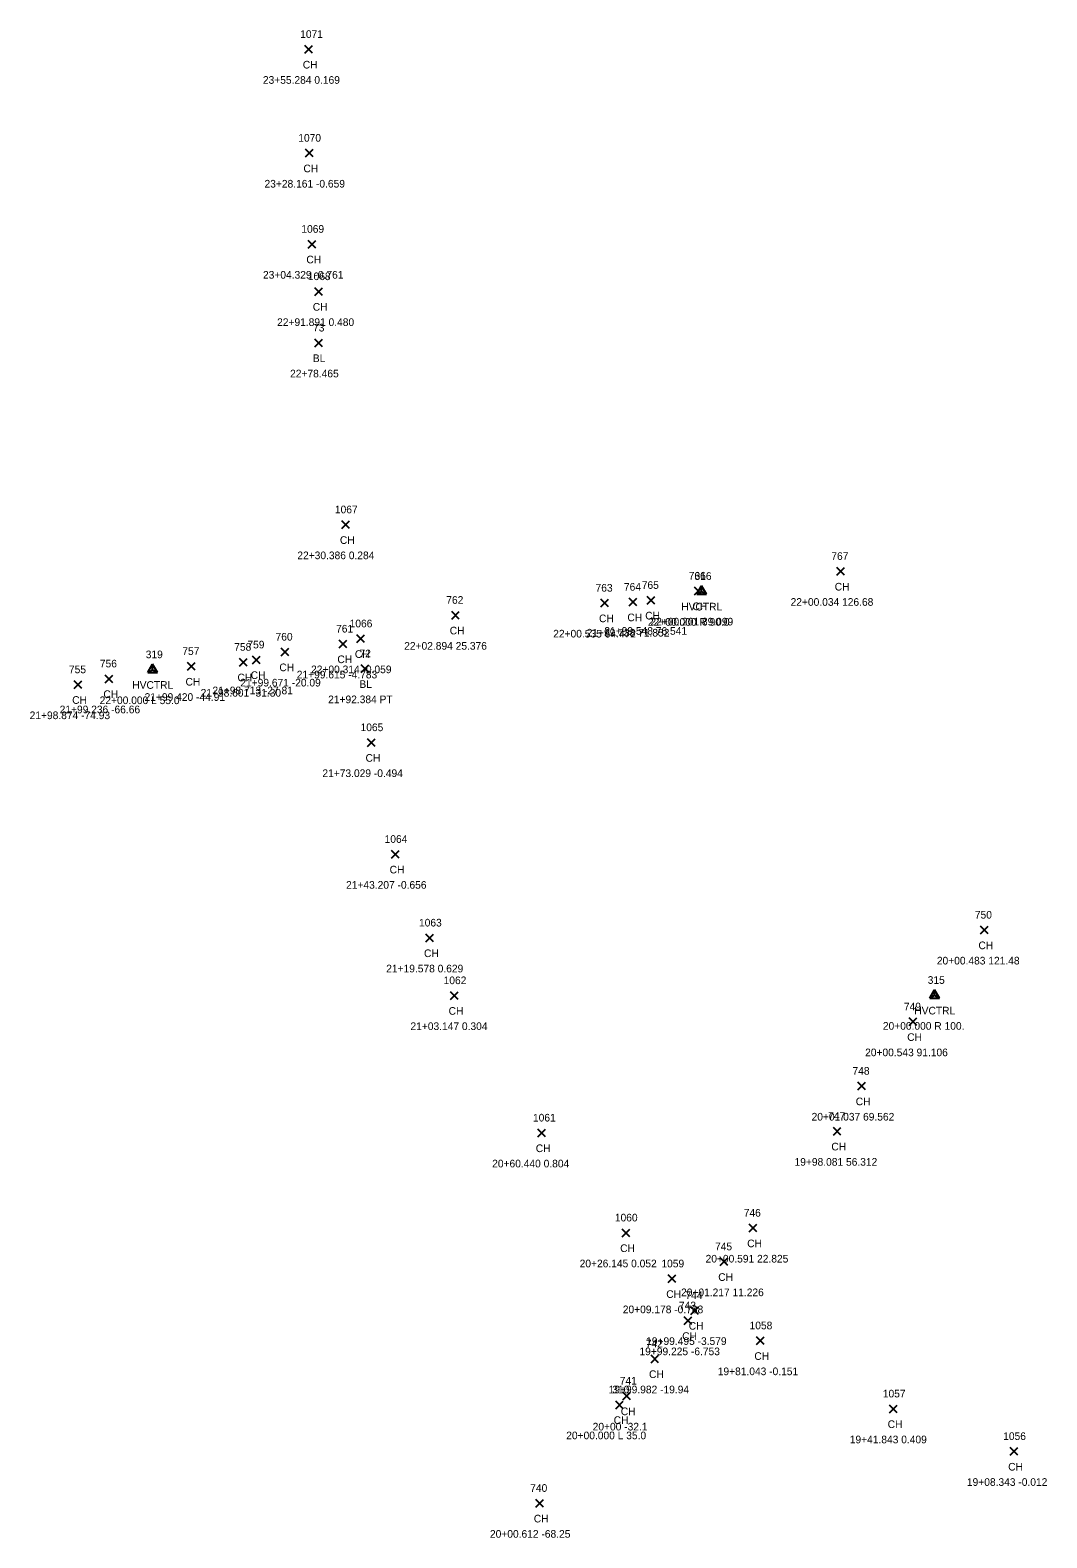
# Model space of a CAD drawing. Extents: x 89316 to 92454, y 84175 to 86051.
# Drawn here: x 90198.7 to 90464.6, y 85155.5 to 85549.8 of the extents above; entities that cross this region are included whole.
import ezdxf

# ---------------------------------------------------------------- set-up
doc = ezdxf.new("R2010")
doc.units = 0
for name, color, linetype in [('C_A', 7, 'Continuous'), ('C_C', 7, 'Continuous'), ('C_I', 7, 'Continuous'), ('C_TIC', 7, 'Continuous'), ('CPSM', 7, 'Continuous'), ('L_A', 7, 'Continuous'), ('L_C', 7, 'Continuous'), ('L_I', 7, 'Continuous'), ('L_TIC', 7, 'Continuous')]:
    doc.layers.add(name, color=color, linetype=linetype)

msp = doc.modelspace()

# ---------------------------------------------------------------- linework, layer by layer
at = {"layer": 'C_TIC'}
for points in [[(90273.17, 85466.95), (90275.17, 85468.95)], [(90275.17, 85466.95), (90273.17, 85468.95)], [(90285.34, 85381.74), (90287.34, 85383.74)], [(90287.34, 85381.74), (90285.34, 85383.74)]]:
    msp.add_lwpolyline(points, dxfattribs=at)
at = {"layer": 'CPSM'}
for p, q in [((90373.08, 85402.27), (90374.33, 85404.43)), ((90373.08, 85402.27), (90374.33, 85402.99)), ((90373.08, 85402.27), (90375.58, 85402.27)), ((90375.58, 85402.27), (90374.33, 85404.43)), ((90374.33, 85402.99), (90374.33, 85404.43)), ((90374.33, 85402.99), (90374.33, 85402.99)), ((90374.33, 85402.99), (90375.58, 85402.27)), ((90229.5, 85381.78), (90230.75, 85383.94)), ((90229.5, 85381.78), (90230.75, 85382.5)), ((90229.5, 85381.78), (90232, 85381.78)), ((90232, 85381.78), (90230.75, 85383.94)), ((90230.75, 85382.5), (90230.75, 85383.94)), ((90230.75, 85382.5), (90230.75, 85382.5)), ((90230.75, 85382.5), (90232, 85381.78)), ((90434.02, 85296.62), (90435.27, 85298.79)), ((90434.02, 85296.62), (90435.27, 85297.34)), ((90434.02, 85296.62), (90436.52, 85296.62)), ((90436.52, 85296.62), (90435.27, 85298.79)), ((90435.27, 85297.34), (90435.27, 85298.79)), ((90435.27, 85297.34), (90435.27, 85297.34)), ((90435.27, 85297.34), (90436.52, 85296.62))]:
    msp.add_line(p, q, dxfattribs=at)
at = {"layer": 'L_TIC'}
for points in [[(90270.55, 85543.73), (90272.55, 85545.73)], [(90272.55, 85543.73), (90270.55, 85545.73)], [(90270.71, 85516.59), (90272.71, 85518.59)], [(90272.71, 85516.59), (90270.71, 85518.59)], [(90271.47, 85492.77), (90273.47, 85494.77)], [(90273.47, 85492.77), (90271.47, 85494.77)], [(90273.16, 85480.39), (90275.16, 85482.39)], [(90275.16, 85480.39), (90273.16, 85482.39)], [(90280.25, 85419.4), (90282.25, 85421.4)], [(90282.25, 85419.4), (90280.25, 85421.4)], [(90409.67, 85407.21), (90411.67, 85409.21)], [(90411.67, 85407.21), (90409.67, 85409.21)], [(90360.1, 85399.64), (90362.1, 85401.64)], [(90362.1, 85399.64), (90360.1, 85401.64)], [(90372.44, 85402.07), (90374.44, 85404.07)], [(90374.44, 85402.07), (90372.44, 85404.07)], [(90308.97, 85395.73), (90310.97, 85397.73)], [(90310.97, 85395.73), (90308.97, 85397.73)], [(90348.01, 85398.92), (90350.01, 85400.92)], [(90350.01, 85398.92), (90348.01, 85400.92)], [(90355.43, 85399.17), (90357.43, 85401.17)], [(90357.43, 85399.17), (90355.43, 85401.17)], [(90279.58, 85388.22), (90281.58, 85390.22)], [(90281.58, 85388.22), (90279.58, 85390.22)], [(90284.16, 85389.58), (90286.16, 85391.58)], [(90286.16, 85389.58), (90284.16, 85391.58)], [(90256.91, 85384.07), (90258.91, 85386.07)], [(90258.91, 85384.07), (90256.91, 85386.07)], [(90264.41, 85386.11), (90266.41, 85388.11)], [(90266.41, 85386.11), (90264.41, 85388.11)], [(90239.88, 85382.35), (90241.88, 85384.35)], [(90241.88, 85382.35), (90239.88, 85384.35)], [(90253.47, 85383.46), (90255.47, 85385.46)], [(90255.47, 85383.46), (90253.47, 85385.46)], [(90210.23, 85377.57), (90212.23, 85379.57)], [(90212.23, 85377.57), (90210.23, 85379.57)], [(90218.38, 85379.1), (90220.38, 85381.1)], [(90220.38, 85379.1), (90218.38, 85381.1)], [(90286.96, 85362.43), (90288.96, 85364.43)], [(90288.96, 85362.43), (90286.96, 85364.43)], [(90293.25, 85333.22), (90295.25, 85335.22)], [(90295.25, 85333.22), (90293.25, 85335.22)], [(90447.25, 85313.41), (90449.25, 85315.41)], [(90449.25, 85313.41), (90447.25, 85315.41)], [(90302.24, 85311.34), (90304.24, 85313.34)], [(90304.24, 85311.34), (90302.24, 85313.34)], [(90308.68, 85296.26), (90310.68, 85298.26)], [(90310.68, 85296.26), (90308.68, 85298.26)], [(90428.62, 85289.41), (90430.62, 85291.41)], [(90430.62, 85289.41), (90428.62, 85291.41)], [(90415.16, 85272.59), (90417.16, 85274.59)], [(90417.16, 85272.59), (90415.16, 85274.59)], [(90331.48, 85260.34), (90333.48, 85262.34)], [(90333.48, 85260.34), (90331.48, 85262.34)], [(90408.79, 85260.78), (90410.79, 85262.78)], [(90410.79, 85260.78), (90408.79, 85262.78)], [(90353.55, 85234.21), (90355.55, 85236.21)], [(90355.55, 85234.21), (90353.55, 85236.21)], [(90386.77, 85235.46), (90388.77, 85237.46)], [(90388.77, 85235.46), (90386.77, 85237.46)], [(90379.2, 85226.66), (90381.2, 85228.66)], [(90381.2, 85226.66), (90379.2, 85228.66)], [(90365.6, 85222.2), (90367.6, 85224.2)], [(90367.6, 85222.2), (90365.6, 85224.2)], [(90369.77, 85211.22), (90371.77, 85213.22)], [(90371.77, 85211.22), (90369.77, 85213.22)], [(90371.48, 85213.91), (90373.48, 85215.91)], [(90373.48, 85213.91), (90371.48, 85215.91)], [(90388.66, 85206), (90390.66, 85208)], [(90390.66, 85206), (90388.66, 85208)], [(90361.1, 85201.25), (90363.1, 85203.25)], [(90363.1, 85201.25), (90361.1, 85203.25)], [(90353.73, 85191.54), (90355.73, 85193.54)], [(90355.73, 85191.54), (90353.73, 85193.54)], [(90351.86, 85189.24), (90353.86, 85191.24)], [(90353.86, 85189.24), (90351.86, 85191.24)], [(90423.5, 85188.18), (90425.5, 85190.18)], [(90425.5, 85188.18), (90423.5, 85190.18)], [(90455.04, 85177.05), (90457.04, 85179.05)], [(90457.04, 85177.05), (90455.04, 85179.05)], [(90330.96, 85163.49), (90332.96, 85165.49)], [(90332.96, 85163.49), (90330.96, 85165.49)]]:
    msp.add_lwpolyline(points, dxfattribs=at)

# ---------------------------------------------------------------- texts
at = {"layer": 'C_A'}
for s, p in [('BL', (90272.66, 85462.95)), ('HVCTRL', (90369.02, 85397.99)), ('HVCTRL', (90225.44, 85377.5)), ('BL', (90284.83, 85377.74)), ('HVCTRL', (90429.96, 85292.34))]:
    msp.add_text(s, height=2, dxfattribs=at).set_placement(p)
at = {"layer": 'C_C'}
for s, p in [('22+78.465', (90266.71, 85458.95)), ('22+00.000 R 90.0', (90360.3, 85393.99)), ('22+00.000 L 55.0', (90216.9, 85373.5)), ('21+92.384 PT', (90276.66, 85373.74)), ('20+00.000 R 100.', (90421.74, 85288.34))]:
    msp.add_text(s, height=2, dxfattribs=at).set_placement(p)
at = {"layer": 'C_I'}
for s, p in [('73', (90272.71, 85470.95)), ('316', (90372.48, 85405.99)), ('319', (90228.95, 85385.5)), ('72', (90284.87, 85385.74)), ('315', (90433.47, 85300.34))]:
    msp.add_text(s, height=2, dxfattribs=at).set_placement(p)
at = {"layer": 'L_A'}
for p in [(90270.04, 85539.73), (90270.2, 85512.59), (90270.96, 85488.77), (90272.65, 85476.39), (90279.74, 85415.4), (90409.15, 85403.21), (90359.59, 85395.64), (90371.93, 85398.07), (90308.46, 85391.73), (90347.5, 85394.92), (90354.92, 85395.17), (90279.07, 85384.22), (90283.65, 85385.58), (90256.4, 85380.07), (90263.9, 85382.11), (90239.37, 85378.35), (90252.95, 85379.46), (90209.72, 85373.57), (90217.87, 85375.1), (90286.45, 85358.43), (90292.74, 85329.22), (90446.74, 85309.41), (90301.73, 85307.34), (90308.17, 85292.26), (90428.11, 85285.41), (90414.65, 85268.59), (90330.97, 85256.34), (90408.27, 85256.78), (90353.04, 85230.21), (90386.26, 85231.46), (90378.69, 85222.66), (90365.09, 85218.2), (90369.26, 85207.22), (90370.97, 85209.91), (90388.14, 85202), (90360.59, 85197.25), (90353.21, 85187.54), (90351.34, 85185.24), (90422.99, 85184.18), (90454.52, 85173.05), (90330.45, 85159.49)]:
    msp.add_text('CH', height=2, dxfattribs=at).set_placement(p)
at = {"layer": 'L_C'}
for s, p in [('23+55.284 0.169', (90259.59, 85535.73)), ('23+28.161 -0.659', (90260.02, 85508.59)), ('23+04.329 -0.761', (90259.62, 85484.77)), ('22+91.891 0.480', (90263.31, 85472.39)), ('22+30.386 0.284', (90268.6, 85411.4)), ('22+00.034 126.68', (90397.61, 85399.21)), ('21+99.548 76.541', (90348.89, 85391.64)), ('22+00.201 89.099', (90360.96, 85394.07)), ('22+02.894 25.376', (90296.55, 85387.73)), ('22+00.535 64.472', (90335.52, 85390.92)), ('21+99.738 71.852', (90344.27, 85391.17)), ('21+99.615 -4.783', (90268.45, 85380.22)), ('22+00.314 -0.059', (90272.19, 85381.58)), ('21+98.713 -27.81', (90246.4, 85376.07)), ('21+99.671 -20.09', (90253.69, 85378.11)), ('21+99.420 -44.91', (90228.65, 85374.35)), ('21+98.601 -31.30', (90243.31, 85375.46)), ('21+98.874 -74.93', (90198.59, 85369.57)), ('21+99.236 -66.66', (90206.44, 85371.1)), ('21+73.029 -0.494', (90275.16, 85354.43)), ('21+43.207 -0.656', (90281.35, 85325.22)), ('20+00.483 121.48', (90435.86, 85305.41)), ('21+19.578 0.629', (90291.85, 85303.34)), ('21+03.147 0.304', (90298.19, 85288.26)), ('20+00.543 91.106', (90417.1, 85281.41)), ('20+01.037 69.562', (90403.1, 85264.59)), ('20+60.440 0.804', (90319.56, 85252.34)), ('19+98.081 56.312', (90398.64, 85252.78)), ('20+26.145 0.052', (90342.44, 85226.21)), ('20+00.591 22.825', (90375.38, 85227.46)), ('20+01.217 11.226', (90368.96, 85218.66)), ('20+09.178 -0.788', (90353.72, 85214.2)), ('19+99.225 -6.753', (90358.08, 85203.22)), ('19+99.495 -3.579', (90359.83, 85205.91)), ('19+81.043 -0.151', (90378.55, 85198)), ('19+99.982 -19.94', (90350.02, 85193.25)), ('20+00 -32.1', (90345.84, 85183.54)), ('20+00.000 L 35.0', (90338.93, 85181.24)), ('19+41.843 0.409', (90413.08, 85180.18)), ('19+08.343 -0.012', (90443.72, 85169.05)), ('20+00.612 -68.25', (90318.98, 85155.49))]:
    msp.add_text(s, height=2, dxfattribs=at).set_placement(p)
at = {"layer": 'L_I'}
for s, p in [('1071', (90269.35, 85547.73)), ('1070', (90268.85, 85520.59)), ('1069', (90269.65, 85496.77)), ('1068', (90271.35, 85484.39)), ('1067', (90278.43, 85423.4)), ('767', (90408.26, 85411.21)), ('765', (90358.69, 85403.64)), ('766', (90370.97, 85406.07)), ('762', (90307.56, 85399.73)), ('763', (90346.6, 85402.92)), ('764', (90354.02, 85403.17)), ('761', (90278.74, 85392.22)), ('1066', (90282.28, 85393.58)), ('759', (90255.54, 85388.07)), ('760', (90262.91, 85390.11)), ('757', (90238.52, 85386.35)), ('758', (90252.1, 85387.46)), ('755', (90208.87, 85381.57)), ('756', (90216.96, 85383.1)), ('1065', (90285.14, 85366.43)), ('1064', (90291.43, 85337.22)), ('750', (90445.8, 85317.41)), ('1063', (90300.42, 85315.34)), ('1062', (90306.86, 85300.26)), ('749', (90427.25, 85293.41)), ('748', (90413.8, 85276.59)), ('1061', (90330.23, 85264.34)), ('747', (90407.42, 85264.78)), ('1060', (90351.65, 85238.21)), ('746', (90385.36, 85239.46)), ('745', (90377.84, 85230.66)), ('1059', (90363.82, 85226.2)), ('743', (90368.41, 85215.22)), ('744', (90370.12, 85217.91)), ('1058', (90386.88, 85210)), ('742', (90359.74, 85205.25)), ('741', (90352.93, 85195.54)), ('310', (90350.97, 85193.24)), ('1057', (90421.73, 85192.18)), ('1056', (90453.21, 85181.05)), ('740', (90329.51, 85167.49))]:
    msp.add_text(s, height=2, dxfattribs=at).set_placement(p)

doc.saveas('drawing.dxf')
